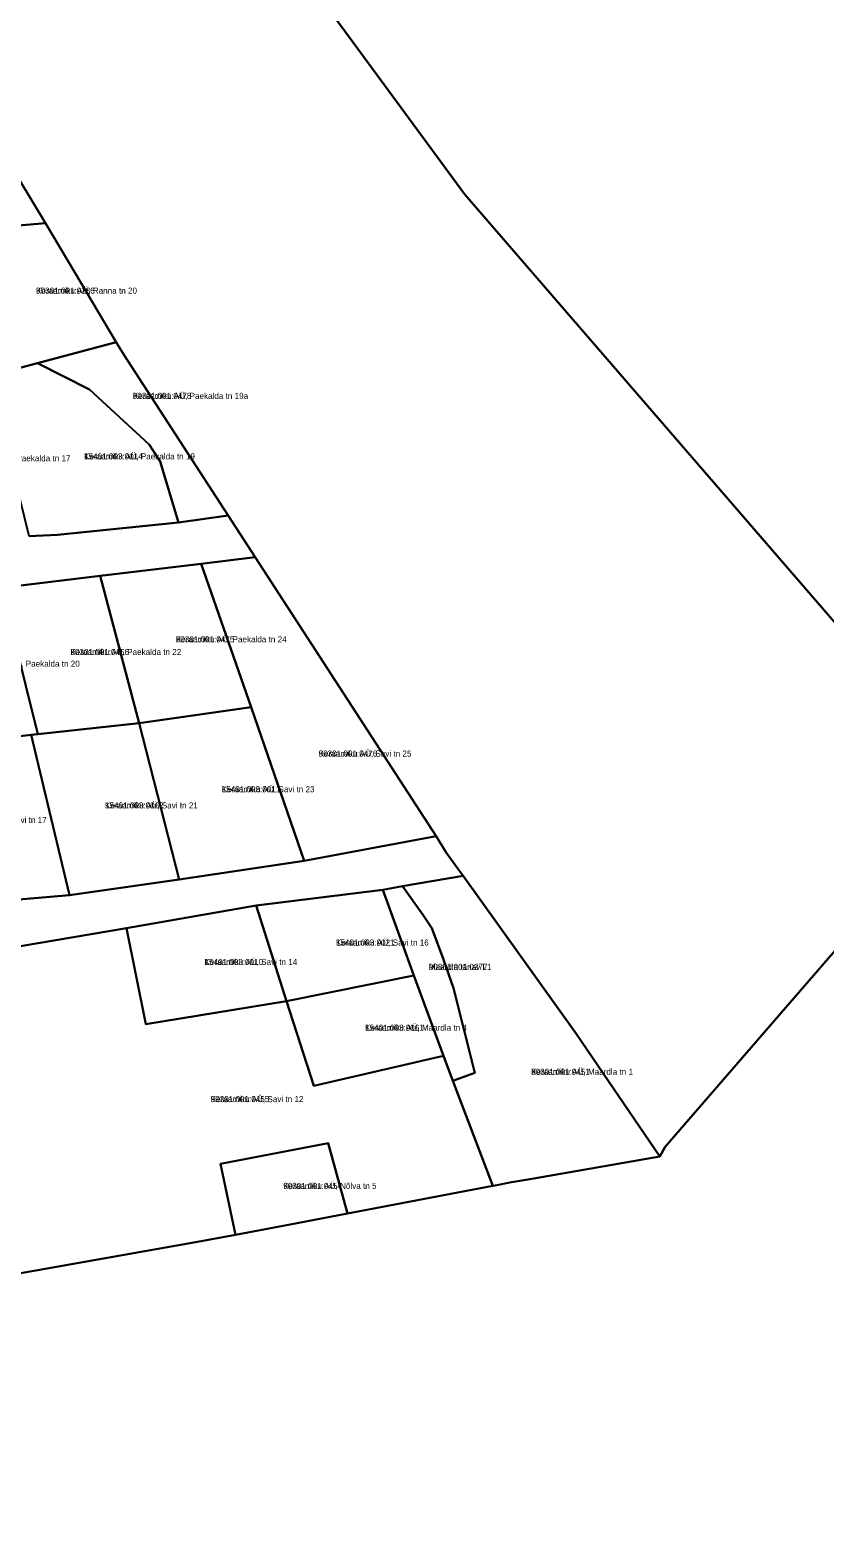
# Model space of a CAD drawing. Extents: x 634518 to 667988, y 6584667 to 6604739.
# Drawn here: x 662172.8 to 662369.4, y 6594554.3 to 6594927.4 of the extents above; entities that cross this region are included whole.
import ezdxf

# ---------------------------------------------------------------- set-up
doc = ezdxf.new("R2010")
doc.units = 0
for name, color, linetype in [('L_AADRESS', 7, 'Continuous'), ('PIIR', 7, 'Continuous'), ('TUNNUS', 7, 'Continuous')]:
    doc.layers.add(name, color=color, linetype=linetype)

msp = doc.modelspace()

# ---------------------------------------------------------------- linework, layer by layer
at = {"layer": 'PIIR'}
for points in [[(662104.25, 6595299.32), (662170.09, 6595328.86), (662326.94, 6595209.37), (662404.32, 6595143.05), (662582.57, 6595011.75), (662625.07, 6594995.26), (662739.56, 6594877.05), (662896.61, 6594721.69), (662904.03, 6594623.41), (662762.45, 6594503.67), (662710.16, 6594477.4), (662559.46, 6594603.27), (662407.03, 6594740.17), (662280.35, 6594886.74), (662090.94, 6595144.56), (662050.58, 6595245.75)], [(662183.9, 6594867.42), (662194.07, 6594850.17), (662174.59, 6594845.03), (662162.77, 6594841.87), (662154.46, 6594877.77), (662176.57, 6594879.64)], [(662195.94, 6594847.18), (662221.81, 6594807.3), (662209.52, 6594805.57), (662204.95, 6594820.68), (662202.25, 6594824.88), (662187.52, 6594838.46), (662174.59, 6594845.03), (662194.07, 6594850.17)], [(662162.77, 6594841.87), (662174.59, 6594845.03), (662187.52, 6594838.46), (662202.25, 6594824.88), (662204.95, 6594820.68), (662209.52, 6594805.57), (662179.59, 6594802.52), (662172.57, 6594802.15)], [(662190.16, 6594792.35), (662215.13, 6594795.37), (662227.52, 6594759.87), (662199.81, 6594755.95)], [(662273.25, 6594727.99), (662240.59, 6594721.84), (662227.52, 6594759.87), (662215.13, 6594795.37), (662228.51, 6594796.96)], [(662165.72, 6594789.4), (662190.16, 6594792.35), (662199.81, 6594755.95), (662174.73, 6594753.23)], [(662149.5, 6594750.24), (662140.59, 6594786.76), (662165.72, 6594789.4), (662174.73, 6594753.23), (662173.04, 6594753.04)], [(662209.64, 6594717.27), (662199.81, 6594755.95), (662227.52, 6594759.87), (662240.59, 6594721.84)], [(662125.18, 6594748.13), (662149.5, 6594750.24), (662173.04, 6594753.04), (662182.52, 6594713.33), (662135.29, 6594709.35)], [(662174.73, 6594753.23), (662199.81, 6594755.95), (662209.64, 6594717.27), (662182.52, 6594713.33), (662173.04, 6594753.04)], [(662260.08, 6594714.67), (662264.94, 6594715.55), (662270.09, 6594708.41), (662272.19, 6594705.19), (662275.06, 6594697.46), (662277.55, 6594690.31), (662282.83, 6594669.37), (662277.42, 6594667.41), (662275.07, 6594673.58), (662267.76, 6594693.5), (662263.46, 6594705.36)], [(662279.92, 6594718.15), (662307.84, 6594679.22), (662314.68, 6594669.18), (662328.61, 6594648.73), (662297.43, 6594643.28), (662292.94, 6594642.5), (662291.93, 6594642.32), (662287.9, 6594641.55), (662287.3, 6594641.44), (662277.42, 6594667.41), (662282.83, 6594669.37), (662277.55, 6594690.31), (662275.06, 6594697.46), (662272.19, 6594705.19), (662270.09, 6594708.41), (662264.94, 6594715.55)], [(662236.27, 6594687.1), (662228.7, 6594710.78), (662260.08, 6594714.67), (662263.46, 6594705.36), (662267.76, 6594693.5)], [(662201.4, 6594681.4), (662196.65, 6594705.21), (662228.7, 6594710.78), (662236.27, 6594687.1)], [(662196.65, 6594705.21), (662201.4, 6594681.4), (662236.27, 6594687.1), (662242.98, 6594666.15), (662275.07, 6594673.58), (662277.42, 6594667.41), (662287.3, 6594641.44), (662251.35, 6594634.61), (662246.53, 6594652.01), (662219.88, 6594646.85), (662223.58, 6594629.34), (662214.23, 6594627.56), (662166.33, 6594619.08), (662165.14, 6594623.17), (662160.09, 6594643.16), (662155.13, 6594663.88), (662149.98, 6594690.46), (662148.5, 6594697.01)], [(662267.76, 6594693.5), (662275.07, 6594673.58), (662242.98, 6594666.15), (662236.27, 6594687.1)], [(662219.88, 6594646.85), (662246.53, 6594652.01), (662251.35, 6594634.61), (662238.85, 6594632.24), (662223.58, 6594629.34)]]:
    msp.add_lwpolyline(points, close=True, dxfattribs=at)
for points in [[(662090.94, 6595144.56), (662280.35, 6594886.74), (662407.03, 6594740.17), (662329.92, 6594651.1), (662328.61, 6594648.73), (662314.68, 6594669.18), (662307.84, 6594679.22), (662279.92, 6594718.15), (662278.97, 6594719.48), (662275.78, 6594723.93), (662273.25, 6594727.99), (662228.51, 6594796.96), (662221.81, 6594807.3), (662195.94, 6594847.18), (662194.07, 6594850.17), (662183.9, 6594867.42), (662176.57, 6594879.64), (662170.09, 6594890.44), (662148.35, 6594926.69), (662074.18, 6595056.38)], [(662170.09, 6594890.44), (662176.57, 6594879.64), (662154.46, 6594877.77)], [(662172.57, 6594802.15), (662179.59, 6594802.52), (662209.52, 6594805.57), (662221.81, 6594807.3), (662228.51, 6594796.96), (662215.13, 6594795.37), (662190.16, 6594792.35), (662165.72, 6594789.4)], [(662010.27, 6594507.9), (661975.47, 6594581.01), (661973.97, 6594583.52), (662007.46, 6594589.64), (662019.64, 6594591.87), (662036.07, 6594594.87), (662038.56, 6594595.33), (662071.21, 6594601.5), (662106.77, 6594608.23), (662132.48, 6594613.08), (662166.33, 6594619.08), (662214.23, 6594627.56), (662223.58, 6594629.34), (662238.85, 6594632.24), (662251.35, 6594634.61), (662287.3, 6594641.44), (662287.9, 6594641.55), (662291.93, 6594642.32), (662292.94, 6594642.5), (662297.43, 6594643.28), (662328.61, 6594648.73), (662329.92, 6594651.1), (662407.03, 6594740.17)], [(662135.29, 6594709.35), (662182.52, 6594713.33), (662209.64, 6594717.27), (662240.59, 6594721.84), (662273.25, 6594727.99), (662275.78, 6594723.93), (662278.97, 6594719.48), (662279.92, 6594718.15), (662264.94, 6594715.55), (662260.08, 6594714.67), (662228.7, 6594710.78), (662196.65, 6594705.21), (662148.5, 6594697.01)]]:
    msp.add_lwpolyline(points, dxfattribs=at)

# ---------------------------------------------------------------- texts
at = {"layer": 'L_AADRESS'}
for s, p in [('Keraamiku AÜ, Ranna tn 20', (662174.27, 6594862.19)), ('Keraamiku AÜ, Paekalda tn 19a', (662198.2, 6594836.15)), ('Keraamiku AÜ, Paekalda tn 17', (662155.36, 6594820.72)), ('Keraamiku AÜ, Paekalda tn 19', (662186.15, 6594821.17)), ('Keraamiku AÜ, Paekalda tn 24', (662208.84, 6594775.92)), ('Keraamiku AÜ, Paekalda tn 20', (662157.66, 6594769.88)), ('Keraamiku AÜ, Paekalda tn 22', (662182.77, 6594772.78)), ('Keraamiku AÜ, Savi tn 25', (662244.19, 6594747.65)), ('Keraamiku AÜ, Savi tn 23', (662220.2, 6594738.83)), ('Keraamiku AÜ, Savi tn 21', (662191.34, 6594734.82)), ('Keraamiku AÜ, Savi tn 17', (662153.93, 6594731.2)), ('Keraamiku AÜ, Savi tn 16', (662248.47, 6594700.89)), ('Keraamiku AÜ, Savi tn 14', (662215.93, 6594696.09)), ('Maardla tänav L1', (662271.45, 6594694.87)), ('Keraamiku AÜ, Maardla tn 4', (662255.69, 6594679.82)), ('Keraamiku AÜ, Maardla tn 1', (662296.77, 6594668.91)), ('Keraamiku AÜ, Savi tn 12', (662217.48, 6594662.15)), ('Keraamiku AÜ, Nõlva tn 5', (662235.43, 6594640.68))]:
    msp.add_text(s, height=1.5, dxfattribs=at).set_placement(p)
at = {"layer": 'TUNNUS'}
for s, p in [('90301:001:0286', (662174.27, 6594862.19)), ('90301:001:0478', (662198.2, 6594836.15)), ('15401:003:0014', (662186.15, 6594821.17)), ('90301:001:0475', (662208.84, 6594775.92)), ('90301:001:0456', (662182.77, 6594772.78)), ('90301:001:0476', (662244.19, 6594747.65)), ('15401:003:0011', (662220.2, 6594738.83)), ('15401:003:0062', (662191.34, 6594734.82)), ('15401:003:0021', (662248.47, 6594700.89)), ('15401:003:0010', (662215.93, 6594696.09)), ('90301:001:0277', (662271.45, 6594694.87)), ('15401:003:0061', (662255.69, 6594679.82)), ('90301:001:0451', (662296.77, 6594668.91)), ('90301:001:0455', (662217.48, 6594662.15)), ('90301:001:0454', (662235.43, 6594640.68))]:
    msp.add_text(s, height=1.5, dxfattribs=at).set_placement(p)

doc.saveas('drawing.dxf')
